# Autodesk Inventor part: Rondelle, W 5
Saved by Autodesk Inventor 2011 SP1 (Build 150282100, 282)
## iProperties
Created: 2010-12
Part Number: Rondelle, W 5
Document SubType Name: Modeling
Designer: eric
Density: 1 g/cm^3
Mass: 0.0318889 g
Surface Area: 1.09403 cm^2
Volume: 0.0318889 cm^3
Author: eric
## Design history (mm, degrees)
feature "Base1"
node "Solide1"
node "Corps solides"
node "Corps surfaciques"
